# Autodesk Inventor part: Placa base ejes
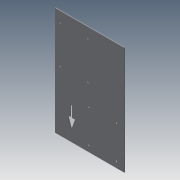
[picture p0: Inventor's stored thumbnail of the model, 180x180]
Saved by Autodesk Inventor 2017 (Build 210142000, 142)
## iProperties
Created: 2019-03
Part Number: Placa base ejes
Material: Generic
Document SubType Name: Modeling
Designer: user
Density: 1 g/cm^3
Appearance: Default
Author: user
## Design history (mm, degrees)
sketch "Sketch1"
  geometry: L1 (448.386, 293.199)-(243.649, 293.199); L2 (243.649, 293.199)-(243.649, -26.801); L3 (243.649, -26.801)-(448.386, -26.801); L4 (448.386, -26.801)-(448.386, 293.199); 1 further point
  constraints: 8 end point, 2 parallel, 1 horizontal, 1 perpendicular
  dimensions: "d2" = 320 distance of L1.end L2.end
extrude "Extrusion1" new body sketch "Sketch1" distance "d0" = 2.43; taper "d1" = 0 deg
sketch "Sketch2"
  geometry: C1 r 2.5 at (-266.835, 9.296) reference; C2 r 2.5 at (-348.835, 9.296) reference; C3 r 2.5 at (-266.835, -88.704) reference; C4 r 2.5 at (-348.835, -88.704) reference; C5 r 2.5 at (-351.835, -150.704) reference; C6 r 2.5 at (-433.835, -150.704) reference; C7 r 2.5 at (-351.835, -262.704) reference; C8 r 2.5 at (-433.835, -262.704) reference; 1 further point
extrude "Extrusion2" cut sketch "Sketch2" stored distance "d3" = 3; taper "d4" = 0 deg
sketch "Sketch3"
  geometry: L1 (-397.639, -36.249)-(-397.639, -67.546); L2 (-397.639, -67.546)-(-403.251, -67.546); L3 (-403.251, -67.546)-(-403.251, -36.249); L4 (-400.445, -4.92)-(-397.639, -4.92); L5 (-411.574, -36.249)-(-389.316, -4.92); L6 (-400.445, -4.92)-(-411.574, -36.249); L7 (-400.445, -4.92)-(-389.316, -36.249); L8 (-389.316, -36.249)-(-400.445, -20.585); L9 (-404.155, -15.363)-(-411.574, -4.92); L10 (-389.316, -36.249)-(-397.639, -36.249); L11 (-403.251, -36.249)-(-411.574, -36.249); 1 further point
  constraints: 22 end point, 3 parallel, 2 horizontal, 2 point on line, 1 midpoint
extrude "Extrusion3" cut sketch "Sketch3" stored distance "d5" = 10; taper "d6" = 0 deg
body "Solid1"
node "Reference1"
node "Reference2"
node "Reference3"
node "Reference4"
node "Reference5"
node "Reference6"
node "Reference7"
node "Reference8"
